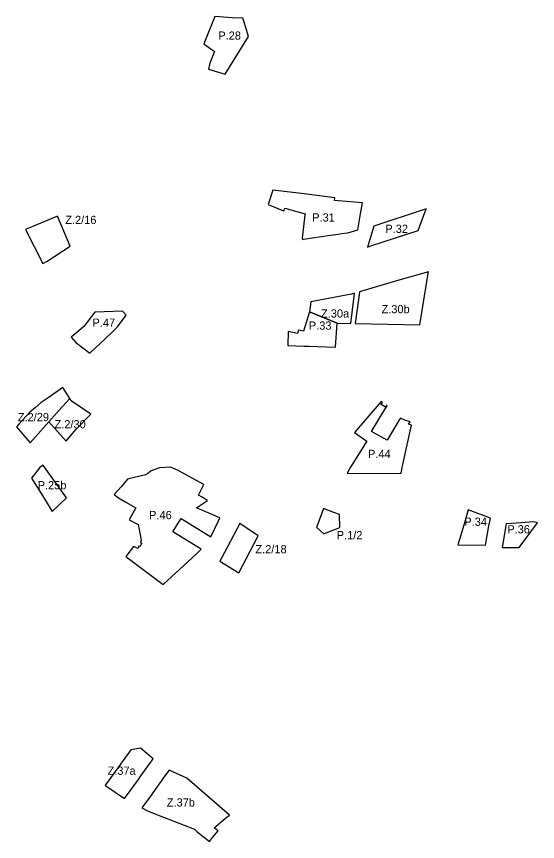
# Model space of a CAD drawing. Extents: x -438701 to -435614, y -1126017 to -1121766.
# Drawn here: x -437854 to -437221, y -1124568 to -1123565 of the extents above; entities that cross this region are included whole.
import ezdxf

# ---------------------------------------------------------------- set-up
doc = ezdxf.new("R2010")
doc.units = 0
for name, color, linetype in [('NAVRH', 7, 'Continuous'), ('STAV', 7, 'Continuous'), ('Vrstva 3', 7, 'Continuous'), ('Vrstva 6', 7, 'Continuous'), ('Vrstva 7', 7, 'Continuous'), ('Vrstva 9', 7, 'Continuous')]:
    doc.layers.add(name, color=color, linetype=linetype)

msp = doc.modelspace()

# ---------------------------------------------------------------- linework, layer by layer
at = {"layer": 'NAVRH'}
for p, q in [((-437822.5, -1123865.5), (-437817.2, -1123862.8)), ((-437353.6, -1123875.6), (-437389.6, -1123886.1)), ((-437364.4, -1123940.3), (-437354.4, -1123880.3)), ((-437354.4, -1123880.3), (-437353.6, -1123875.6)), ((-437438.1, -1123903.9), (-437442.7, -1123938.5)), ((-437498.4, -1123924.6), (-437464.6, -1123938.1)), ((-437442.7, -1123938.5), (-437364.4, -1123940.3)), ((-437798, -1124016.3), (-437815.9, -1124028.9)), ((-437789.6, -1124029.7), (-437798, -1124016.3)), ((-437815.9, -1124028.9), (-437824.3, -1124034.8)), ((-437789.6, -1124029.7), (-437802.4, -1124044)), ((-437802.4, -1124044), (-437789.6, -1124029.7)), ((-437787.9, -1124032.5), (-437789.6, -1124029.7)), ((-437764.1, -1124048.9), (-437787.9, -1124032.5)), ((-437831.1, -1124040.7), (-437838, -1124046.4)), ((-437824.3, -1124034.8), (-437831.1, -1124040.7)), ((-437838, -1124046.4), (-437851.3, -1124061)), ((-437802.4, -1124044), (-437815.2, -1124058.3)), ((-437815.2, -1124058.3), (-437802.4, -1124044)), ((-437782.4, -1124067.6), (-437764.1, -1124048.9)), ((-437851.3, -1124061), (-437854.3, -1124064.2)), ((-437837.6, -1124083.5), (-437815.2, -1124058.3)), ((-437815.2, -1124058.3), (-437793.9, -1124081.6)), ((-437854.3, -1124064.2), (-437837.6, -1124083.5)), ((-437793.9, -1124081.6), (-437782.4, -1124067.6)), ((-437583.1, -1124181.5), (-437605.3, -1124223.9)), ((-437605.3, -1124223.9), (-437607.2, -1124227.4)), ((-437607.2, -1124227.4), (-437584.1, -1124241.7)), ((-437715.4, -1124456.7), (-437722.7, -1124466.9)), ((-437703.8, -1124454.9), (-437715.4, -1124456.7)), ((-437688.4, -1124467.8), (-437703.8, -1124454.9)), ((-437722.7, -1124466.9), (-437744.9, -1124497.6)), ((-437698.8, -1124482.3), (-437688.4, -1124467.8)), ((-437668.8, -1124481.4), (-437668.9, -1124481.3)), ((-437647.4, -1124491.1), (-437668.8, -1124481.4)), ((-437595.5, -1124536.1), (-437647.4, -1124491.1)), ((-437681, -1124498.2), (-437691.6, -1124513)), ((-437678.7, -1124495), (-437681, -1124498.2)), ((-437723, -1124516), (-437721.7, -1124514.1)), ((-437691.6, -1124513), (-437701.9, -1124527.4)), ((-437701.9, -1124527.4), (-437695.2, -1124531)), ((-437695.2, -1124531), (-437688.2, -1124533.8)), ((-437688.2, -1124533.8), (-437637.9, -1124553.3)), ((-437614.2, -1124551.4), (-437599.9, -1124539.4)), ((-437599.9, -1124539.4), (-437595.5, -1124536.1)), ((-437637.9, -1124553.3), (-437635, -1124555.8)), ((-437609.4, -1124555.2), (-437614.2, -1124551.4)), ((-437635, -1124555.8), (-437619.8, -1124568.1)), ((-437619.8, -1124568.1), (-437616, -1124563.4)), ((-437616, -1124563.4), (-437609.4, -1124555.2))]:
    msp.add_line(p, q, dxfattribs=at)
for points in [[(-437817.2, -1123862.8), (-437789, -1123844.8), (-437804.6, -1123808.1), (-437843.4, -1123824.2), (-437822.5, -1123865.5)], [(-437389.6, -1123886.1), (-437437.6, -1123900.1), (-437438.1, -1123903.9)], [(-437464.6, -1123938.1), (-437448.2, -1123938.4), (-437444, -1123905.5), (-437443.6, -1123901.8), (-437447.2, -1123902.9)], [(-437447.2, -1123902.9), (-437496.6, -1123912.2), (-437498.4, -1123924.6)], [(-437584.1, -1124241.7), (-437560.7, -1124196.6), (-437583.1, -1124181.5)], [(-437721.7, -1124514.1), (-437706.2, -1124492.6), (-437703.1, -1124488.2), (-437698.8, -1124482.3)], [(-437668.9, -1124481.3), (-437675.1, -1124490), (-437678.7, -1124495)], [(-437668.9, -1124481.3), (-437668.9, -1124481.3)], [(-437744.9, -1124497.6), (-437746.6, -1124499.6), (-437745.8, -1124500.4), (-437723, -1124516)]]:
    msp.add_lwpolyline(points, dxfattribs=at)
at = {"layer": 'Vrstva 3'}
for p, q in [((-437613.5, -1123565.5), (-437626.5, -1123598.5)), ((-437592.3, -1123567.3), (-437613.5, -1123565.5)), ((-437579.5, -1123567.5), (-437592.3, -1123567.3)), ((-437577.1, -1123573.4), (-437579.5, -1123567.5)), ((-437572.3, -1123589.7), (-437577.1, -1123573.4)), ((-437600.9, -1123635.4), (-437572.3, -1123589.7)), ((-437626.5, -1123598.5), (-437613.9, -1123608.1)), ((-437613.9, -1123608.1), (-437619.2, -1123622)), ((-437619.2, -1123622), (-437621, -1123629.3)), ((-437621, -1123629.3), (-437600.9, -1123635.4)), ((-437542.9, -1123776.6), (-437548.7, -1123793.9)), ((-437508, -1123780.8), (-437542.9, -1123776.6)), ((-437467.5, -1123785.7), (-437508, -1123780.8)), ((-437467.9, -1123789), (-437467.5, -1123785.7)), ((-437434, -1123792), (-437467.9, -1123789)), ((-437436.3, -1123805.5), (-437434, -1123792)), ((-437548.7, -1123793.9), (-437529.8, -1123801.5)), ((-437529.8, -1123801.5), (-437529.6, -1123801.6)), ((-437529.6, -1123801.6), (-437528.3, -1123798.3)), ((-437528.3, -1123798.3), (-437503.7, -1123805.2)), ((-437356.4, -1123799.3), (-437420, -1123820.2)), ((-437366.4, -1123825.6), (-437356.4, -1123799.3)), ((-437503.9, -1123806.7), (-437506.9, -1123831.4)), ((-437503.7, -1123805.2), (-437503.9, -1123806.7)), ((-437438.9, -1123820), (-437436.3, -1123805.5)), ((-437439.7, -1123824.7), (-437438.9, -1123820)), ((-437507, -1123832), (-437507.3, -1123834.5)), ((-437506.9, -1123831.4), (-437507, -1123832)), ((-437505.5, -1123836.3), (-437472.9, -1123831.2)), ((-437451.6, -1123828.3), (-437439.7, -1123824.7)), ((-437423.7, -1123844.4), (-437366.4, -1123825.6)), ((-437507.3, -1123834.5), (-437506.6, -1123836.4)), ((-437506.6, -1123836.5), (-437505.5, -1123836.3)), ((-437506.6, -1123836.4), (-437506.6, -1123836.5)), ((-437759, -1123925), (-437772.4, -1123942.1)), ((-437725.7, -1123923.6), (-437759, -1123925)), ((-437731.6, -1123942.6), (-437721.1, -1123928.6)), ((-437721.1, -1123928.6), (-437725.7, -1123923.6)), ((-437464.6, -1123938.1), (-437498.4, -1123924.6)), ((-437737.2, -1123948.3), (-437731.6, -1123942.6)), ((-437466.9, -1123967.2), (-437464.6, -1123938.1)), ((-437784.9, -1123952.6), (-437788, -1123955.2)), ((-437746.2, -1123956.7), (-437737.2, -1123948.3)), ((-437765.4, -1123974.8), (-437746.2, -1123956.7)), ((-437411.3, -1124033.2), (-437443.6, -1124071.1)), ((-437409.6, -1124034.4), (-437411.3, -1124033.2)), ((-437411.2, -1124037.1), (-437409.6, -1124034.4)), ((-437406.1, -1124040.1), (-437411.2, -1124037.1)), ((-437409.5, -1124047.6), (-437403.9, -1124038.6)), ((-437404.8, -1124037.9), (-437406.1, -1124040.1)), ((-437403.9, -1124038.6), (-437404.8, -1124037.9)), ((-437423.1, -1124069.7), (-437409.5, -1124047.6)), ((-437392, -1124060.4), (-437403.9, -1124080.4)), ((-437389.3, -1124055.8), (-437392, -1124060.4)), ((-437387.9, -1124053.5), (-437389.3, -1124055.8)), ((-437382.5, -1124056.2), (-437387.9, -1124053.5)), ((-437384.9, -1124110.1), (-437374.5, -1124062)), ((-437376.1, -1124058.3), (-437382.5, -1124056.2)), ((-437377.9, -1124061), (-437376.1, -1124058.3)), ((-437374.5, -1124062), (-437377.9, -1124061)), ((-437443.6, -1124071.1), (-437428.6, -1124081.5)), ((-437403.9, -1124080.4), (-437423.1, -1124069.7)), ((-437428.6, -1124081.5), (-437448.3, -1124113.3)), ((-437822, -1124110.9), (-437825.8, -1124113.5)), ((-437820.3, -1124113), (-437822, -1124110.9)), ((-437793.5, -1124150.3), (-437820.3, -1124113)), ((-437667.2, -1124113.3), (-437680.4, -1124114.2)), ((-437658.5, -1124116.8), (-437667.2, -1124113.3)), ((-437448.3, -1124113.3), (-437450, -1124116.1)), ((-437385.7, -1124113.4), (-437384.9, -1124110.1)), ((-437825.8, -1124113.5), (-437836, -1124126.4)), ((-437697.4, -1124122.7), (-437719.4, -1124127.6)), ((-437694.7, -1124120.8), (-437697.4, -1124122.7)), ((-437690.7, -1124117.8), (-437694.7, -1124120.8)), ((-437680.4, -1124114.2), (-437690.7, -1124117.8)), ((-437626.6, -1124134.2), (-437658.5, -1124116.8)), ((-437450, -1124116.1), (-437452.7, -1124120.6)), ((-437452.7, -1124120.6), (-437387.2, -1124120.7)), ((-437387.2, -1124120.7), (-437386.7, -1124118.3)), ((-437386.7, -1124118.3), (-437385.7, -1124113.4)), ((-437721.5, -1124130.2), (-437725, -1124134.5)), ((-437719.4, -1124127.6), (-437721.5, -1124130.2)), ((-437727.2, -1124137.2), (-437735.5, -1124146.6)), ((-437725, -1124134.5), (-437727.2, -1124137.2)), ((-437633, -1124147.1), (-437626.6, -1124134.2)), ((-437810.8, -1124167.2), (-437793.5, -1124150.3)), ((-437735.5, -1124146.6), (-437730.3, -1124150.6)), ((-437730.3, -1124150.6), (-437721.6, -1124155.6)), ((-437628.8, -1124149.7), (-437633, -1124147.1)), ((-437622.2, -1124153.8), (-437628.8, -1124149.7)), ((-437721.6, -1124155.6), (-437709.3, -1124162.6)), ((-437635.7, -1124162.7), (-437622.2, -1124153.8)), ((-437621.4, -1124168.8), (-437635.7, -1124162.7)), ((-437481.2, -1124163.4), (-437489.6, -1124186.5)), ((-437468.8, -1124168.1), (-437481.2, -1124163.4)), ((-437607.2, -1124174.9), (-437621.4, -1124168.8)), ((-437461.7, -1124170.7), (-437468.8, -1124168.1)), ((-437461.5, -1124186.5), (-437461.7, -1124170.7)), ((-437305.7, -1124164.9), (-437310.1, -1124180.7)), ((-437278.5, -1124175.1), (-437305.7, -1124164.9)), ((-437706.5, -1124182.7), (-437703.8, -1124197.4)), ((-437659.8, -1124184.4), (-437654.1, -1124175.7)), ((-437654.1, -1124175.7), (-437618.1, -1124198)), ((-437618.1, -1124198), (-437608.9, -1124178.5)), ((-437608.9, -1124178.5), (-437607.2, -1124174.9)), ((-437310.1, -1124180.7), (-437313.3, -1124191.7)), ((-437280.2, -1124184.6), (-437279.3, -1124179.3)), ((-437279.3, -1124179.3), (-437278.5, -1124175.1)), ((-437259.5, -1124182.2), (-437264.2, -1124211)), ((-437241.1, -1124181), (-437259.5, -1124182.2)), ((-437243.7, -1124210.8), (-437221.3, -1124180.9)), ((-437226.1, -1124179.8), (-437241.1, -1124181)), ((-437221.3, -1124180.9), (-437226.1, -1124179.8)), ((-437664.5, -1124191.6), (-437659.8, -1124184.4)), ((-437630, -1124213), (-437664.5, -1124191.6)), ((-437489.6, -1124186.5), (-437489.5, -1124186.6)), ((-437489.5, -1124186.6), (-437481, -1124194.3)), ((-437480.9, -1124194.4), (-437478, -1124193.2)), ((-437478, -1124193.2), (-437461.5, -1124186.5)), ((-437313.3, -1124191.7), (-437318, -1124207.6)), ((-437284.4, -1124207.8), (-437280.2, -1124184.6)), ((-437703.8, -1124197.4), (-437702.9, -1124202.5)), ((-437702.9, -1124202.5), (-437703.8, -1124205)), ((-437481, -1124194.3), (-437480.9, -1124194.4)), ((-437705.5, -1124209.1), (-437706.6, -1124211.9)), ((-437703.9, -1124209.8), (-437705.5, -1124209.1)), ((-437702.2, -1124205.6), (-437703.9, -1124209.8)), ((-437703.8, -1124205), (-437702.2, -1124205.6)), ((-437636.2, -1124218.8), (-437630, -1124213)), ((-437318, -1124207.6), (-437284.4, -1124207.8)), ((-437264.2, -1124211), (-437243.7, -1124210.8)), ((-437721.6, -1124221.9), (-437676.2, -1124255.9)), ((-437676.2, -1124255.9), (-437636.2, -1124218.8))]:
    msp.add_line(p, q, dxfattribs=at)
for points in [[(-437420, -1123820.2), (-437427.9, -1123845.7), (-437423.7, -1123844.4)], [(-437472.9, -1123831.2), (-437463.1, -1123829.9), (-437459.4, -1123829.4), (-437451.6, -1123828.3)], [(-437498.4, -1123924.6), (-437505.5, -1123947.9), (-437511.5, -1123946.5), (-437512.7, -1123950.8), (-437524.4, -1123948.2), (-437524.6, -1123965.3)], [(-437772.4, -1123942.1), (-437781.6, -1123949.9), (-437784.9, -1123952.6)], [(-437788, -1123955.2), (-437782.2, -1123961.6), (-437765.4, -1123974.8)], [(-437524.6, -1123965.3), (-437505.2, -1123966), (-437498.5, -1123966.2), (-437466.9, -1123967.2)], [(-437836, -1124126.4), (-437820.4, -1124151.7), (-437810.8, -1124167.2)], [(-437709.3, -1124162.6), (-437717.3, -1124177.3), (-437706.5, -1124182.7)], [(-437706.6, -1124211.9), (-437712.1, -1124209.7), (-437721.6, -1124221.9)]]:
    msp.add_lwpolyline(points, dxfattribs=at)
at = {"layer": 'Vrstva 6'}
for p, q in [((-437822.5, -1123865.5), (-437817.2, -1123862.8)), ((-437353.6, -1123875.6), (-437389.6, -1123886.1)), ((-437364.4, -1123940.3), (-437354.4, -1123880.3)), ((-437354.4, -1123880.3), (-437353.6, -1123875.6)), ((-437438.1, -1123903.9), (-437442.7, -1123938.5)), ((-437498.4, -1123924.6), (-437464.6, -1123938.1)), ((-437442.7, -1123938.5), (-437364.4, -1123940.3)), ((-437798, -1124016.3), (-437815.9, -1124028.9)), ((-437789.6, -1124029.7), (-437798, -1124016.3)), ((-437815.9, -1124028.9), (-437824.3, -1124034.8)), ((-437802.4, -1124044), (-437789.6, -1124029.7)), ((-437789.6, -1124029.7), (-437802.4, -1124044)), ((-437787.9, -1124032.5), (-437789.6, -1124029.7)), ((-437764.1, -1124048.9), (-437787.9, -1124032.5)), ((-437831.1, -1124040.7), (-437838, -1124046.4)), ((-437824.3, -1124034.8), (-437831.1, -1124040.7)), ((-437838, -1124046.4), (-437851.3, -1124061)), ((-437815.2, -1124058.3), (-437802.4, -1124044)), ((-437802.4, -1124044), (-437815.2, -1124058.3)), ((-437782.4, -1124067.6), (-437764.1, -1124048.9)), ((-437851.3, -1124061), (-437854.3, -1124064.2)), ((-437837.6, -1124083.5), (-437815.2, -1124058.3)), ((-437815.2, -1124058.3), (-437793.9, -1124081.6)), ((-437854.3, -1124064.2), (-437837.6, -1124083.5)), ((-437793.9, -1124081.6), (-437782.4, -1124067.6)), ((-437583.1, -1124181.5), (-437605.3, -1124223.9)), ((-437605.3, -1124223.9), (-437607.2, -1124227.4)), ((-437607.2, -1124227.4), (-437584.1, -1124241.7)), ((-437715.4, -1124456.7), (-437722.7, -1124466.9)), ((-437703.8, -1124454.9), (-437715.4, -1124456.7)), ((-437688.4, -1124467.8), (-437703.8, -1124454.9)), ((-437722.7, -1124466.9), (-437744.9, -1124497.6)), ((-437698.8, -1124482.3), (-437688.4, -1124467.8)), ((-437668.8, -1124481.4), (-437668.9, -1124481.3)), ((-437647.4, -1124491.1), (-437668.8, -1124481.4)), ((-437595.5, -1124536.1), (-437647.4, -1124491.1)), ((-437681, -1124498.2), (-437691.6, -1124513)), ((-437678.7, -1124495), (-437681, -1124498.2)), ((-437723, -1124516), (-437721.7, -1124514.1)), ((-437691.6, -1124513), (-437701.9, -1124527.4)), ((-437701.9, -1124527.4), (-437695.2, -1124531)), ((-437695.2, -1124531), (-437688.2, -1124533.8)), ((-437688.2, -1124533.8), (-437637.9, -1124553.3)), ((-437614.2, -1124551.4), (-437599.9, -1124539.4)), ((-437599.9, -1124539.4), (-437595.5, -1124536.1)), ((-437637.9, -1124553.3), (-437635, -1124555.8)), ((-437609.4, -1124555.2), (-437614.2, -1124551.4)), ((-437635, -1124555.8), (-437619.8, -1124568.1)), ((-437619.8, -1124568.1), (-437616, -1124563.4)), ((-437616, -1124563.4), (-437609.4, -1124555.2))]:
    msp.add_line(p, q, dxfattribs=at)
for points in [[(-437817.2, -1123862.8), (-437789, -1123844.8), (-437804.6, -1123808.1), (-437843.4, -1123824.2), (-437822.5, -1123865.5)], [(-437389.6, -1123886.1), (-437437.6, -1123900.1), (-437438.1, -1123903.9)], [(-437464.6, -1123938.1), (-437448.2, -1123938.4), (-437444, -1123905.5), (-437443.6, -1123901.8), (-437447.2, -1123902.9)], [(-437447.2, -1123902.9), (-437496.6, -1123912.2), (-437498.4, -1123924.6)], [(-437584.1, -1124241.7), (-437560.7, -1124196.6), (-437583.1, -1124181.5)], [(-437721.7, -1124514.1), (-437706.2, -1124492.6), (-437703.1, -1124488.2), (-437698.8, -1124482.3)], [(-437668.9, -1124481.3), (-437675.1, -1124490), (-437678.7, -1124495)], [(-437744.9, -1124497.6), (-437746.6, -1124499.6), (-437745.8, -1124500.4), (-437723, -1124516)]]:
    msp.add_lwpolyline(points, dxfattribs=at)
at = {"layer": 'Vrstva 7'}
for p, q in [((-437613.5, -1123565.5), (-437626.5, -1123598.5)), ((-437592.3, -1123567.3), (-437613.5, -1123565.5)), ((-437579.5, -1123567.5), (-437592.3, -1123567.3)), ((-437577.1, -1123573.4), (-437579.5, -1123567.5)), ((-437572.3, -1123589.7), (-437577.1, -1123573.4)), ((-437600.9, -1123635.4), (-437572.3, -1123589.7)), ((-437626.5, -1123598.5), (-437613.9, -1123608.1)), ((-437613.9, -1123608.1), (-437619.2, -1123622)), ((-437619.2, -1123622), (-437621, -1123629.3)), ((-437621, -1123629.3), (-437600.9, -1123635.4)), ((-437542.9, -1123776.6), (-437548.7, -1123793.9)), ((-437508, -1123780.8), (-437542.9, -1123776.6)), ((-437467.5, -1123785.7), (-437508, -1123780.8)), ((-437467.9, -1123789), (-437467.5, -1123785.7)), ((-437434, -1123792), (-437467.9, -1123789)), ((-437436.3, -1123805.5), (-437434, -1123792)), ((-437548.7, -1123793.9), (-437529.8, -1123801.5)), ((-437529.8, -1123801.5), (-437529.6, -1123801.6)), ((-437529.6, -1123801.6), (-437528.3, -1123798.3)), ((-437528.3, -1123798.3), (-437503.7, -1123805.2)), ((-437356.4, -1123799.3), (-437420, -1123820.2)), ((-437366.4, -1123825.6), (-437356.4, -1123799.3)), ((-437503.9, -1123806.7), (-437506.9, -1123831.4)), ((-437503.7, -1123805.2), (-437503.9, -1123806.7)), ((-437438.9, -1123820), (-437436.3, -1123805.5)), ((-437439.7, -1123824.7), (-437438.9, -1123820)), ((-437507, -1123832), (-437507.3, -1123834.5)), ((-437506.9, -1123831.4), (-437507, -1123832)), ((-437505.5, -1123836.3), (-437472.9, -1123831.2)), ((-437451.6, -1123828.3), (-437439.7, -1123824.7)), ((-437423.7, -1123844.4), (-437366.4, -1123825.6)), ((-437507.3, -1123834.5), (-437506.6, -1123836.4)), ((-437506.6, -1123836.5), (-437505.5, -1123836.3)), ((-437506.6, -1123836.4), (-437506.6, -1123836.5)), ((-437759, -1123925), (-437772.4, -1123942.1)), ((-437725.7, -1123923.6), (-437759, -1123925)), ((-437731.6, -1123942.6), (-437721.1, -1123928.6)), ((-437721.1, -1123928.6), (-437725.7, -1123923.6)), ((-437464.6, -1123938.1), (-437498.4, -1123924.6)), ((-437737.2, -1123948.3), (-437731.6, -1123942.6)), ((-437466.9, -1123967.2), (-437464.6, -1123938.1)), ((-437784.9, -1123952.6), (-437788, -1123955.2)), ((-437746.2, -1123956.7), (-437737.2, -1123948.3)), ((-437765.4, -1123974.8), (-437746.2, -1123956.7)), ((-437411.3, -1124033.2), (-437443.6, -1124071.1)), ((-437409.6, -1124034.4), (-437411.3, -1124033.2)), ((-437411.2, -1124037.1), (-437409.6, -1124034.4)), ((-437406.1, -1124040.1), (-437411.2, -1124037.1)), ((-437409.5, -1124047.6), (-437403.9, -1124038.6)), ((-437404.8, -1124037.9), (-437406.1, -1124040.1)), ((-437403.9, -1124038.6), (-437404.8, -1124037.9)), ((-437423.1, -1124069.7), (-437409.5, -1124047.6)), ((-437392, -1124060.4), (-437403.9, -1124080.4)), ((-437389.3, -1124055.8), (-437392, -1124060.4)), ((-437387.9, -1124053.5), (-437389.3, -1124055.8)), ((-437382.5, -1124056.2), (-437387.9, -1124053.5)), ((-437384.9, -1124110.1), (-437374.5, -1124062)), ((-437376.1, -1124058.3), (-437382.5, -1124056.2)), ((-437377.9, -1124061), (-437376.1, -1124058.3)), ((-437374.5, -1124062), (-437377.9, -1124061)), ((-437443.6, -1124071.1), (-437428.6, -1124081.5)), ((-437403.9, -1124080.4), (-437423.1, -1124069.7)), ((-437428.6, -1124081.5), (-437448.3, -1124113.3)), ((-437822, -1124110.9), (-437825.8, -1124113.5)), ((-437820.3, -1124113), (-437822, -1124110.9)), ((-437793.5, -1124150.3), (-437820.3, -1124113)), ((-437667.2, -1124113.3), (-437680.4, -1124114.2)), ((-437658.5, -1124116.8), (-437667.2, -1124113.3)), ((-437448.3, -1124113.3), (-437450, -1124116.1)), ((-437385.7, -1124113.4), (-437384.9, -1124110.1)), ((-437825.8, -1124113.5), (-437836, -1124126.4)), ((-437697.4, -1124122.7), (-437719.4, -1124127.6)), ((-437694.7, -1124120.8), (-437697.4, -1124122.7)), ((-437690.7, -1124117.8), (-437694.7, -1124120.8)), ((-437680.4, -1124114.2), (-437690.7, -1124117.8)), ((-437626.6, -1124134.2), (-437658.5, -1124116.8)), ((-437450, -1124116.1), (-437452.7, -1124120.6)), ((-437452.7, -1124120.6), (-437387.2, -1124120.7)), ((-437387.2, -1124120.7), (-437386.7, -1124118.3)), ((-437386.7, -1124118.3), (-437385.7, -1124113.4)), ((-437721.5, -1124130.2), (-437725, -1124134.5)), ((-437719.4, -1124127.6), (-437721.5, -1124130.2)), ((-437727.2, -1124137.2), (-437735.5, -1124146.6)), ((-437725, -1124134.5), (-437727.2, -1124137.2)), ((-437633, -1124147.1), (-437626.6, -1124134.2)), ((-437810.8, -1124167.2), (-437793.5, -1124150.3)), ((-437735.5, -1124146.6), (-437730.3, -1124150.6)), ((-437730.3, -1124150.6), (-437721.6, -1124155.6)), ((-437628.8, -1124149.7), (-437633, -1124147.1)), ((-437622.2, -1124153.8), (-437628.8, -1124149.7)), ((-437721.6, -1124155.6), (-437709.3, -1124162.6)), ((-437635.7, -1124162.7), (-437622.2, -1124153.8)), ((-437621.4, -1124168.8), (-437635.7, -1124162.7)), ((-437481.2, -1124163.4), (-437489.6, -1124186.5)), ((-437468.8, -1124168.1), (-437481.2, -1124163.4)), ((-437607.2, -1124174.9), (-437621.4, -1124168.8)), ((-437461.7, -1124170.7), (-437468.8, -1124168.1)), ((-437461.5, -1124186.5), (-437461.7, -1124170.7)), ((-437305.7, -1124164.9), (-437310.1, -1124180.7)), ((-437278.5, -1124175.1), (-437305.7, -1124164.9)), ((-437706.5, -1124182.7), (-437703.8, -1124197.4)), ((-437659.8, -1124184.4), (-437654.1, -1124175.7)), ((-437654.1, -1124175.7), (-437618.1, -1124198)), ((-437618.1, -1124198), (-437608.9, -1124178.5)), ((-437608.9, -1124178.5), (-437607.2, -1124174.9)), ((-437310.1, -1124180.7), (-437313.3, -1124191.7)), ((-437280.2, -1124184.6), (-437279.3, -1124179.3)), ((-437279.3, -1124179.3), (-437278.5, -1124175.1)), ((-437259.5, -1124182.2), (-437264.2, -1124211)), ((-437241.1, -1124181), (-437259.5, -1124182.2)), ((-437243.7, -1124210.8), (-437221.3, -1124180.9)), ((-437226.1, -1124179.8), (-437241.1, -1124181)), ((-437221.3, -1124180.9), (-437226.1, -1124179.8)), ((-437664.5, -1124191.6), (-437659.8, -1124184.4)), ((-437630, -1124213), (-437664.5, -1124191.6)), ((-437489.6, -1124186.5), (-437489.5, -1124186.6)), ((-437489.5, -1124186.6), (-437481, -1124194.3)), ((-437480.9, -1124194.4), (-437478, -1124193.2)), ((-437478, -1124193.2), (-437461.5, -1124186.5)), ((-437313.3, -1124191.7), (-437318, -1124207.6)), ((-437284.4, -1124207.8), (-437280.2, -1124184.6)), ((-437703.8, -1124197.4), (-437702.9, -1124202.5)), ((-437702.9, -1124202.5), (-437703.8, -1124205)), ((-437481, -1124194.3), (-437480.9, -1124194.4)), ((-437705.5, -1124209.1), (-437706.6, -1124211.9)), ((-437703.9, -1124209.8), (-437705.5, -1124209.1)), ((-437702.2, -1124205.6), (-437703.9, -1124209.8)), ((-437703.8, -1124205), (-437702.2, -1124205.6)), ((-437636.2, -1124218.8), (-437630, -1124213)), ((-437318, -1124207.6), (-437284.4, -1124207.8)), ((-437264.2, -1124211), (-437243.7, -1124210.8)), ((-437721.6, -1124221.9), (-437676.2, -1124255.9)), ((-437676.2, -1124255.9), (-437636.2, -1124218.8))]:
    msp.add_line(p, q, dxfattribs=at)
for points in [[(-437420, -1123820.2), (-437427.9, -1123845.7), (-437423.7, -1123844.4)], [(-437472.9, -1123831.2), (-437463.1, -1123829.9), (-437459.4, -1123829.4), (-437451.6, -1123828.3)], [(-437498.4, -1123924.6), (-437505.5, -1123947.9), (-437511.5, -1123946.5), (-437512.7, -1123950.8), (-437524.4, -1123948.2), (-437524.6, -1123965.3)], [(-437772.4, -1123942.1), (-437781.6, -1123949.9), (-437784.9, -1123952.6)], [(-437788, -1123955.2), (-437782.2, -1123961.6), (-437765.4, -1123974.8)], [(-437524.6, -1123965.3), (-437505.2, -1123966), (-437498.5, -1123966.2), (-437466.9, -1123967.2)], [(-437836, -1124126.4), (-437820.4, -1124151.7), (-437810.8, -1124167.2)], [(-437709.3, -1124162.6), (-437717.3, -1124177.3), (-437706.5, -1124182.7)], [(-437706.6, -1124211.9), (-437712.1, -1124209.7), (-437721.6, -1124221.9)]]:
    msp.add_lwpolyline(points, dxfattribs=at)

# ---------------------------------------------------------------- texts
at = {"layer": 'STAV'}
for s, p in [('P.28', (-437609.1, -1123593.7)), ('P.31', (-437495, -1123814.7)), ('P.32', (-437406.1, -1123828.5)), ('P.47', (-437762, -1123942.6)), ('P.33', (-437499.1, -1123946.1)), ('P.44', (-437427.2, -1124102.1)), ('P.25b', (-437828.6, -1124140.1)), ('P.46', (-437693.2, -1124176.4)), ('P.34', (-437310.2, -1124184.5)), ('P.1/2', (-437465.2, -1124200.8)), ('P.36', (-437258, -1124193.7))]:
    msp.add_text(s, height=10, dxfattribs=at).set_placement(p)
at = {"layer": 'Vrstva 9'}
for s, p in [('Z.2/16', (-437795.1, -1123817.7)), ('Z.30a', (-437484.3, -1123931.4)), ('Z.30b', (-437410.8, -1123926.1)), ('Z.2/29', (-437852.7, -1124057.3)), ('Z.2/30', (-437808.1, -1124066)), ('Z.2/18', (-437564, -1124217.8)), ('Z.37a', (-437743.7, -1124487.1)), ('Z.37b', (-437671.7, -1124525.7))]:
    msp.add_text(s, height=10, dxfattribs=at).set_placement(p)

doc.saveas('drawing.dxf')
